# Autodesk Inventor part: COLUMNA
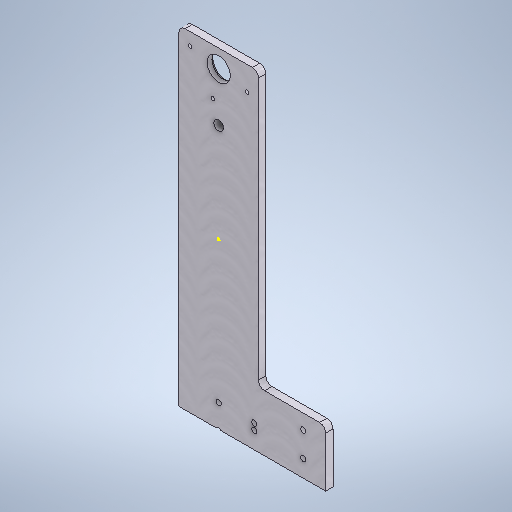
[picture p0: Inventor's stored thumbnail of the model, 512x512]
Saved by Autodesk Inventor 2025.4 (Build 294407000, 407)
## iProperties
Created: 2026-04
Part Number: COLUMNA
Material: Aluminum 6061, Welded
Document SubType Name: Modeling
Designer: PC
Density: 2.7 g/cm^3
Appearance: Weld - Aluminum
Author: PC
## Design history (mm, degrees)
sketch "Sketch1"
  geometry: L1 (32.5, -135)-(-32.5, -135); L2 (-32.5, -135)-(-32.5, 135); L3 (-32.5, 135)-(32.5, 135); L4 (32.5, 135)-(32.5, -135); L5 (32.5, -135)-(-32.5, 135); L6 (-32.5, -135)-(32.5, 135); L7 (-32.5, -135)-(87.5, -135); L8 (87.5, -135)-(87.5, -88.9); L9 (87.5, -88.9)-(-32.5, -88.9); L10 (-32.5, -88.9)-(-32.5, -135); 3 further points
  constraints: 20 end point, 4 parallel, 2 horizontal, 2 midpoint, 2 perpendicular
  dimensions: "d0" = 65 distance of L2.end L3.end; "d1" = 270 distance of L1.end L2.end; "d2" = 120 distance of L9.end L8.end; "d3" = 46.1 distance of L8.end L7.end
extrude "Extrusion1" new body sketch "Sketch1" distance "d4" = 6; taper "d5" = 0 deg
feature "Face Fillet1" dims "d6" = 5
fillet "Fillet1" dims "d7" = 5
sketch "Sketch2"
  geometry: C1 r 4 at (0, 80.178); C2 r 9.5 at (0, 120.178); 1 further point
  constraints: 2 centre point
  dimensions: "d8" = 8 diameter of C1; "d9" = 19 diameter of C2; "d10" = 40 distance of C1.centre C2.centre
extrude "Extrusion2" cut sketch "Sketch2" extent not by distance; stored distance "d11" = 0; taper "d12" = 0 deg
sketch "Sketch3"
  geometry: C1 r 1.5 at (-4.679, 96.884); C2 r 9.5 at (0, 120.178) reference; C3 r 1.5 at (-23.294, 124.856); C4 r 1.5 at (23.294, 115.498); 1 further point
  constraints: 3 centre point
  dimensions: "d13" = 3 diameter of C1; "d14" = 23.759 distance of C2.centre C1.centre; "d15" = 3 diameter of C3; "d16" = 3 diameter of C4; "d17" = 33.6 distance of C3.centre C1.centre; "d18" = 23.759 distance of C2.centre C3.centre; "d19" = 33.6 distance of C1.centre C4.centre; "d20" = 23.759 distance of C4.centre C2.centre
extrude "Extrusion3" cut sketch "Sketch3" distance "d21" = 10; taper "d22" = 0 deg
sketch "Sketch4"
  geometry: 1 further point
sketch "Sketch5"
  geometry: C1 r 9.5 at (0, 120.178) reference; C2 r 11 at (0, 120.178); 1 further point
  constraints: 1 centre point, 1 coincident
  dimensions: "d23" = 22 diameter of C2
extrude "Extrusion4" cut sketch "Sketch5" distance "d24" = 2; taper "d25" = 0 deg
sketch "Sketch6"
  geometry: L1 (32.5, -135)-(-87.5, -135) reference; L2 (-82.5, -88.9)-(-37.5, -88.9) reference; L3 (-69.16, -135)-(-69.16, -126.6); L4 (-69.16, -126.6)-(-69.16, -124.2); L5 (-69.16, -124.2)-(-69.16, -118); L6 (-69.16, -118)-(-69.16, -115.6); L7 (-69.16, -115.6)-(-69.16, -106.6); L8 (-69.16, -106.6)-(-69.16, -104.2); L9 (-69.16, -104.2)-(-69.16, -97.8); L10 (-69.16, -97.8)-(-69.16, -95.4); C1 r 2.2 at (-69.16, -121.1); C2 r 2.2 at (-29.16, -121.1); C3 r 2.2 at (-69.16, -101); C4 r 2.2 at (-29.16, -116); C5 r 2.2 at (0, -116); C6 r 2.2 at (0, -136.1); 2 further points
  constraints: 16 end point, 6 centre point, 2 midpoint, 2 point on line, 11 other
  dimensions: "d26" = 8.4 distance of L3.start L3.end; "d27" = 2.4 distance of L3.end L4.end; "d28" = 6.2 distance of L4.end L5.end; "d29" = 2.4 distance of L5.end L6.end; "d30" = 9 distance of L6.end L7.end; "d31" = 2.4 distance of L7.end L8.end; "d32" = 6.4 distance of L8.end L9.end; "d33" = 2.4 distance of L9.end L10.end; "d34" = 4.4 diameter of C1; "d35" = 4.4 diameter of C2; "d36" = 40 distance of C2.centre C1.centre; "d37" = 4.4 diameter of C5; "d38" = 4.4 diameter of C6
extrude "Extrusion5" cut sketch "Sketch6" distance "d39" = 6; taper "d40" = 0 deg
body "Solid1"
